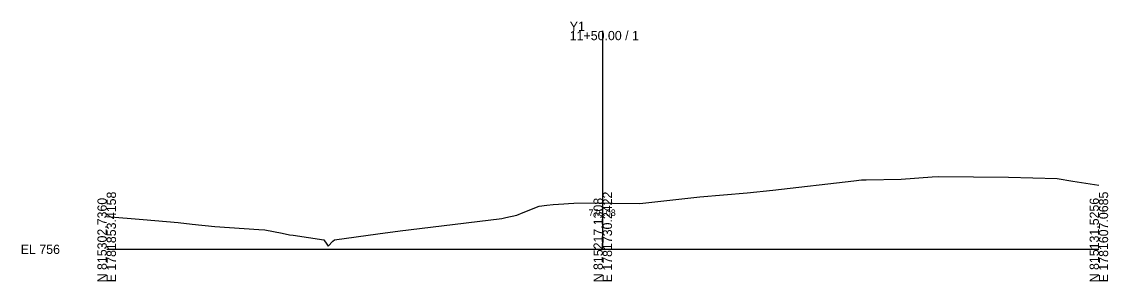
# Model space of a CAD drawing. Extents: x -26 to 3603, y -10 to 9847.
# Drawn here: x -25.7 to 302.8, y 1490.3 to 1569 of the extents above; entities that cross this region are included whole.
import ezdxf

# ---------------------------------------------------------------- set-up
doc = ezdxf.new("R2010")
doc.units = 0
for name, color, linetype in [('Exist Cross Section Cell', 7, 'Continuous'), ('Exist XS Center Line Elevation Label', 7, 'Continuous'), ('Exist XS Ground Line', 7, 'Continuous')]:
    doc.layers.add(name, color=color, linetype=linetype)

msp = doc.modelspace()

# ---------------------------------------------------------------- linework, layer by layer
at = {"layer": 'Exist Cross Section Cell'}
for p, q in [((150, 1500), (150, 1566.18)), ((0, 1500), (150, 1500)), ((150, 1500), (300, 1500))]:
    msp.add_line(p, q, dxfattribs=at)
at = {"layer": 'Exist XS Ground Line'}
for p, q in [((229.63, 1521.08), (240.2, 1521.23)), ((240.2, 1521.23), (249.55, 1521.96)), ((249.55, 1521.96), (251.46, 1522.06)), ((251.46, 1522.06), (272.65, 1521.82)), ((272.65, 1521.82), (287.35, 1521.46)), ((287.35, 1521.46), (292.12, 1520.65)), ((193.68, 1517.14), (201.38, 1517.89)), ((201.38, 1517.89), (225.87, 1520.78)), ((225.87, 1520.78), (228.21, 1521.09)), ((228.21, 1521.09), (229.63, 1521.08)), ((292.12, 1520.65), (300, 1519.47)), ((161.22, 1513.9), (179.35, 1515.95)), ((179.35, 1515.95), (193.68, 1517.14)), ((125.93, 1511.16), (130.75, 1513.03)), ((130.75, 1513.03), (133.12, 1513.38)), ((133.12, 1513.38), (134.99, 1513.55)), ((134.99, 1513.55), (138.25, 1513.81)), ((138.25, 1513.81), (139.61, 1513.91)), ((139.61, 1513.91), (141.2, 1513.94)), ((141.2, 1513.94), (150.1, 1514.08)), ((150.1, 1514.08), (152.97, 1514.03)), ((152.97, 1514.03), (161.22, 1513.9)), ((0, 1509.95), (11.03, 1509.01)), ((11.03, 1509.01), (21.57, 1508.1)), ((21.57, 1508.1), (25.84, 1507.65)), ((97.94, 1506.69), (119.48, 1509.37)), ((119.48, 1509.37), (120.71, 1509.63)), ((120.71, 1509.63), (123.99, 1510.38)), ((123.99, 1510.38), (125.93, 1511.16)), ((25.84, 1507.65), (32.73, 1506.9)), ((32.73, 1506.9), (45.98, 1506.01)), ((45.98, 1506.01), (47.81, 1505.88)), ((47.81, 1505.88), (53.05, 1504.9)), ((53.05, 1504.9), (55.24, 1504.44)), ((68.91, 1502.89), (81.99, 1504.73)), ((81.99, 1504.73), (88.74, 1505.56)), ((88.74, 1505.56), (97.94, 1506.69)), ((55.24, 1504.44), (56.41, 1504.31)), ((56.41, 1504.31), (65.62, 1502.89)), ((65.62, 1502.89), (66.6, 1501.54)), ((66.6, 1501.54), (66.98, 1500.96)), ((66.98, 1500.96), (68.41, 1502.46)), ((68.41, 1502.46), (68.91, 1502.89))]:
    msp.add_line(p, q, dxfattribs=at)

# ---------------------------------------------------------------- texts
at = {"layer": 'Exist Cross Section Cell'}
for s, p in [('Y1', (140, 1566.18)), ('11+50.00 / 1', (140, 1563.38)), ('EL 756', (-26, 1498.6))]:
    msp.add_text(s, height=2.8, dxfattribs=at).set_placement(p)
for s, p in [('N 815302.7360', (0, 1490)), ('E 1781853.4158', (2.8, 1490)), ('N 815217.1308', (150, 1490)), ('E 1781730.2422', (152.8, 1490)), ('N 815131.5256', (300, 1490)), ('E 1781607.0685', (302.8, 1490))]:
    msp.add_text(s, height=2.8, rotation=90, dxfattribs=at).set_placement(p)
at = {"layer": 'Exist XS Center Line Elevation Label'}
msp.add_text('770.08', height=2, dxfattribs=at).set_placement((145.73, 1510.08))

doc.saveas('drawing.dxf')
